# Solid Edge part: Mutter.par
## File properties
Dokumentum tartalom típus: 0
Last saved by: ahadarics
Revision: 76
Sűrűség: 0,000 kg/m^3
Pontosság: 0,990
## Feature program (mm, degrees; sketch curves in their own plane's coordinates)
base feature "unnamed BaseFeature 1"
thread "unnamed Thread 1"
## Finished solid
Body 1: solid body, 23 faces, 46 edges, 24 vertices.
  Faces by surface: cone 14, plane 8, cylinder 1
  Edges by curve: spline 24, circle 16, line 6
Bounding box of the edges (mm): 7.000 x 21.939 x 19.000, from (0, -10.9697, -9.5) to (7, 10.9697, 9.5).
Cylindrical faces by radius (mm): R5.3235 x1
Conical faces (half-angle, radius in mm at the cone's reference point): 60 deg R5.6618 x2, 60 deg R10.2348 x12
Planar faces by outward normal: +x 1, +z 1, -x 1, -z 1, oblique 4
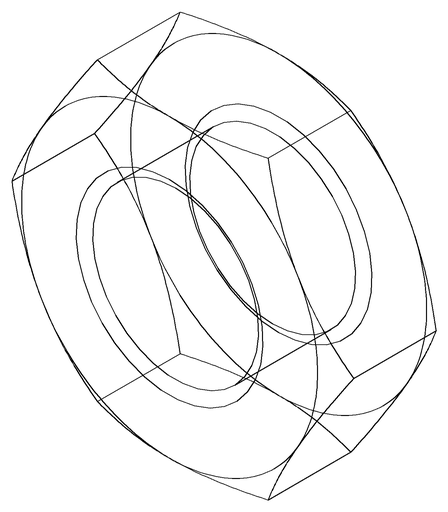
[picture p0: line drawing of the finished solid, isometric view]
